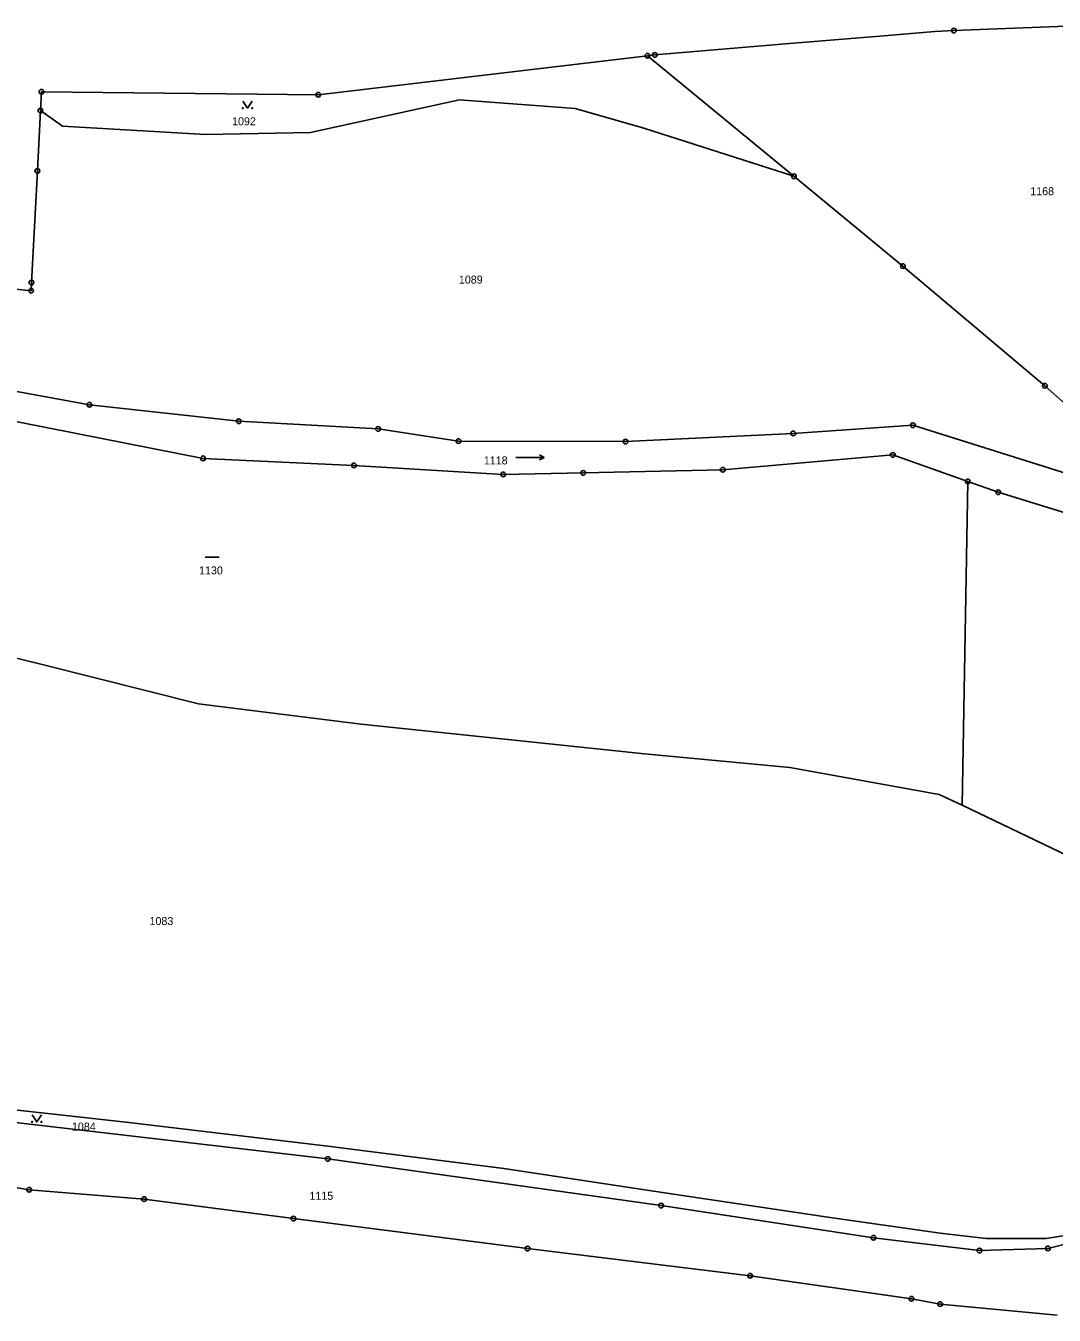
# Model space of a CAD drawing. Extents: x -758887 to -754328, y -1031688 to -1029144.
# Drawn here: x -758653.5 to -758435, y -1029424.1 to -1029150.2 of the extents above; entities that cross this region are included whole.
import ezdxf
from ezdxf.enums import TextEntityAlignment as Align

# ---------------------------------------------------------------- set-up
doc = ezdxf.new("R2010")
doc.units = 0
doc.header["$LTSCALE"] = 0.68
for name, color, linetype, lineweight in [('1', 7, 'Continuous', 25), ('3', 7, 'Continuous', 25), ('8', 7, 'Continuous', 25)]:
    doc.layers.add(name, color=color, linetype=linetype, lineweight=lineweight)
doc.layers.add('2', color=7, linetype='Continuous')

msp = doc.modelspace()

# ---------------------------------------------------------------- linework, layer by layer
at = {"layer": '1'}
for p, q in [((-758591.38, -1029164.83), (-758521.43, -1029156.56)), ((-758521.43, -1029156.56), (-758519.87, -1029156.38)), ((-758490.33, -1029182.16), (-758521.43, -1029156.56)), ((-758650.17, -1029164.18), (-758591.38, -1029164.83)), ((-758453.37, -1029246.98), (-758454.59, -1029315.76))]:
    msp.add_line(p, q, dxfattribs=at)
for points in [[(-758519.87, -1029156.38), (-758490.37, -1029153.89), (-758473.85, -1029152.5), (-758472.04, -1029152.35), (-758460.36, -1029151.36), (-758456.33, -1029151.2), (-758430.56, -1029150.18)], [(-758652.3, -1029204.73), (-758651.05, -1029181.01), (-758650.38, -1029168.19), (-758650.17, -1029164.18)], [(-758490.33, -1029182.16), (-758522.21, -1029171.95), (-758536.79, -1029167.73), (-758561.33, -1029165.94), (-758593.01, -1029172.82), (-758615.35, -1029173.29), (-758645.7, -1029171.51), (-758650.38, -1029168.19)], [(-758401.47, -1029250.78), (-758402.78, -1029249.98), (-758413.29, -1029245.97), (-758417.57, -1029242.53), (-758425.95, -1029236.54), (-758437, -1029226.65), (-758467.17, -1029201.22), (-758490.33, -1029182.16)], [(-758821.62, -1029188.2), (-758652.39, -1029206.45), (-758652.3, -1029204.73)], [(-758821.62, -1029188.2), (-758803.54, -1029192.38), (-758764.19, -1029202.23), (-758728.57, -1029211.45), (-758684.41, -1029222.59), (-758639.98, -1029230.68), (-758608.27, -1029234.2), (-758578.65, -1029235.81), (-758561.56, -1029238.41), (-758526.08, -1029238.52), (-758490.44, -1029236.79), (-758465.04, -1029235.05), (-758428.34, -1029246.54), (-758404, -1029251.92), (-758401.73, -1029252.26)], [(-758834.16, -1029193.62), (-758829.67, -1029194.67), (-758783.26, -1029204.7), (-758753.09, -1029212.59), (-758712.72, -1029222.54), (-758682.47, -1029229.13), (-758654.22, -1029234.5), (-758615.83, -1029242.07), (-758583.78, -1029243.56), (-758552.06, -1029245.48), (-758535.07, -1029245.15), (-758505.45, -1029244.51), (-758469.3, -1029241.34), (-758453.37, -1029246.98)], [(-758454.59, -1029315.76), (-758459.43, -1029313.45), (-758491.2, -1029307.77), (-758522.07, -1029304.83), (-758552.45, -1029301.67), (-758582.24, -1029298.51), (-758616.81, -1029294.25), (-758650.06, -1029285.87), (-758692.1, -1029275.51), (-758721.03, -1029272.45), (-758750.11, -1029264.69), (-758779.62, -1029256.62), (-758811.36, -1029247.64), (-758835.21, -1029242.62), (-758835.84, -1029268.97)], [(-758390.16, -1029265.19), (-758418.21, -1029258.11), (-758446.92, -1029249.26), (-758453.37, -1029246.98)], [(-758454.59, -1029315.76), (-758427.08, -1029328.92), (-758412.67, -1029338.97), (-758404.39, -1029347.29), (-758392.05, -1029348.07)], [(-758876.17, -1029350.61), (-758872.04, -1029354.94), (-758867.03, -1029356.46), (-758737.18, -1029373.09), (-758669.17, -1029381.61), (-758589.35, -1029390.89), (-758518.53, -1029400.82), (-758473.41, -1029407.66), (-758450.9, -1029410.38), (-758436.36, -1029409.91), (-758427.27, -1029407.66), (-758420.59, -1029404.23), (-758412.65, -1029398.73), (-758406.6, -1029388.71)], [(-758837.95, -1029357.1), (-758837.26, -1029357.18), (-758803.09, -1029362.25), (-758770.49, -1029366.4), (-758737.29, -1029370.89), (-758703.46, -1029375.15), (-758669.37, -1029378.99), (-758631.59, -1029383.16), (-758589.33, -1029388.17), (-758551.96, -1029392.92), (-758517.28, -1029398.2), (-758482.61, -1029403.35), (-758459.21, -1029406.64), (-758449.44, -1029407.81), (-758436.76, -1029407.83), (-758429.11, -1029406.62), (-758421.76, -1029403.35), (-758412.4, -1029396.06), (-758406.6, -1029388.71)], [(-758434.38, -1029424.1), (-758459.22, -1029421.73), (-758465.35, -1029420.59), (-758499.63, -1029415.71), (-758546.9, -1029409.94), (-758596.65, -1029403.58), (-758628.38, -1029399.43), (-758652.79, -1029397.45), (-758691.65, -1029390.95), (-758706.46, -1029388.73), (-758731.24, -1029385.5), (-758752.58, -1029383.1), (-758778.82, -1029383.44), (-758795.46, -1029382.32), (-758811.39, -1029378.56), (-758824.75, -1029372.42), (-758837.03, -1029368.67), (-758840, -1029368.31)]]:
    msp.add_lwpolyline(points, dxfattribs=at)
at = {"layer": '3'}
for p, q in [((-758543.403, -1029241.859), (-758544.38, -1029242.36)), ((-758615.408, -1029263.07), (-758612.408, -1029263.07))]:
    msp.add_line(p, q, dxfattribs=at)
for points in [[(-758607.41, -1029166.179), (-758606.41, -1029167.68), (-758605.41, -1029166.179)], [(-758549.403, -1029241.859), (-758543.403, -1029241.859), (-758544.38, -1029241.357)], [(-758652.17, -1029381.529), (-758651.17, -1029383.03), (-758650.17, -1029381.529)]]:
    msp.add_lwpolyline(points, dxfattribs=at)
for centre in [(-758607.41, -1029167.6795), (-758605.41, -1029167.6795), (-758652.17, -1029383.0295), (-758650.17, -1029383.0295)]:
    msp.add_circle(centre, 0.1, dxfattribs=at)
at = {"layer": '8'}
for centre, radius in [((-758456.33, -1029151.1999), 0.5), ((-758456.33, -1029151.1999), 0.0303), ((-758521.43, -1029156.5599), 0.5), ((-758521.43, -1029156.5599), 0.0303), ((-758519.87, -1029156.3799), 0.5), ((-758519.87, -1029156.3799), 0.0303), ((-758650.17, -1029164.1799), 0.5), ((-758650.17, -1029164.1799), 0.0303), ((-758591.38, -1029164.8299), 0.5), ((-758591.38, -1029164.8299), 0.0303), ((-758650.38, -1029168.1899), 0.5), ((-758650.38, -1029168.1899), 0.0303), ((-758651.05, -1029181.0099), 0.5), ((-758651.05, -1029181.0099), 0.0303), ((-758490.33, -1029182.1599), 0.5), ((-758490.33, -1029182.1599), 0.0303), ((-758467.17, -1029201.2199), 0.5), ((-758467.17, -1029201.2199), 0.0303), ((-758652.3, -1029204.7299), 0.5), ((-758652.3, -1029204.7299), 0.0303), ((-758652.39, -1029206.4499), 0.5), ((-758652.39, -1029206.4499), 0.0303), ((-758437, -1029226.6499), 0.5), ((-758437, -1029226.6499), 0.0303), ((-758639.98, -1029230.6799), 0.5), ((-758639.98, -1029230.6799), 0.0303), ((-758608.27, -1029234.1999), 0.5), ((-758608.27, -1029234.1999), 0.0303), ((-758465.04, -1029235.0499), 0.5), ((-758465.04, -1029235.0499), 0.0303), ((-758578.65, -1029235.8099), 0.5), ((-758578.65, -1029235.8099), 0.0303), ((-758561.56, -1029238.4099), 0.5), ((-758490.44, -1029236.7899), 0.5), ((-758490.44, -1029236.7899), 0.0303), ((-758561.56, -1029238.4099), 0.0303), ((-758526.08, -1029238.5199), 0.5), ((-758526.08, -1029238.5199), 0.0303), ((-758615.83, -1029242.0699), 0.5), ((-758615.83, -1029242.0699), 0.0303), ((-758583.78, -1029243.5599), 0.5), ((-758469.3, -1029241.3399), 0.5), ((-758469.3, -1029241.3399), 0.0303), ((-758583.78, -1029243.5599), 0.0303), ((-758552.06, -1029245.4799), 0.5), ((-758552.06, -1029245.4799), 0.0303), ((-758535.07, -1029245.1499), 0.5), ((-758535.07, -1029245.1499), 0.0303), ((-758505.45, -1029244.5099), 0.5), ((-758505.45, -1029244.5099), 0.0303), ((-758453.37, -1029246.9799), 0.5), ((-758453.37, -1029246.9799), 0.0303), ((-758446.92, -1029249.2599), 0.5), ((-758446.92, -1029249.2599), 0.0303), ((-758589.35, -1029390.8899), 0.5), ((-758589.35, -1029390.8899), 0.0303), ((-758652.79, -1029397.4499), 0.5), ((-758652.79, -1029397.4499), 0.0303), ((-758628.38, -1029399.4299), 0.5), ((-758628.38, -1029399.4299), 0.0303), ((-758518.53, -1029400.8199), 0.5), ((-758518.53, -1029400.8199), 0.0303), ((-758596.65, -1029403.5799), 0.5), ((-758596.65, -1029403.5799), 0.0303), ((-758473.41, -1029407.6599), 0.5), ((-758473.41, -1029407.6599), 0.0303), ((-758546.9, -1029409.9399), 0.5), ((-758546.9, -1029409.9399), 0.0303), ((-758450.9, -1029410.3799), 0.5), ((-758450.9, -1029410.3799), 0.0303), ((-758436.36, -1029409.9099), 0.5), ((-758436.36, -1029409.9099), 0.0303), ((-758499.63, -1029415.7099), 0.5), ((-758499.63, -1029415.7099), 0.0303), ((-758465.35, -1029420.5899), 0.5), ((-758465.35, -1029420.5899), 0.0303), ((-758459.22, -1029421.7299), 0.5), ((-758459.22, -1029421.7299), 0.0303)]:
    msp.add_circle(centre, radius, dxfattribs=at)

# ---------------------------------------------------------------- texts
at = {"layer": '2'}
for s, p in [('1092', (-758607.15, -1029171.316)), ('1168', (-758437.58, -1029186.166)), ('1089', (-758558.97, -1029204.946)), ('1118', (-758553.66, -1029243.366)), ('1130', (-758614.17, -1029266.726)), ('1083', (-758624.69, -1029341.216)), ('1084', (-758641.17, -1029384.876)), ('1115', (-758590.71, -1029399.586))]:
    msp.add_text(s, height=1.7, dxfattribs=at).set_placement(p, align=Align.CENTER)

doc.saveas('drawing.dxf')
